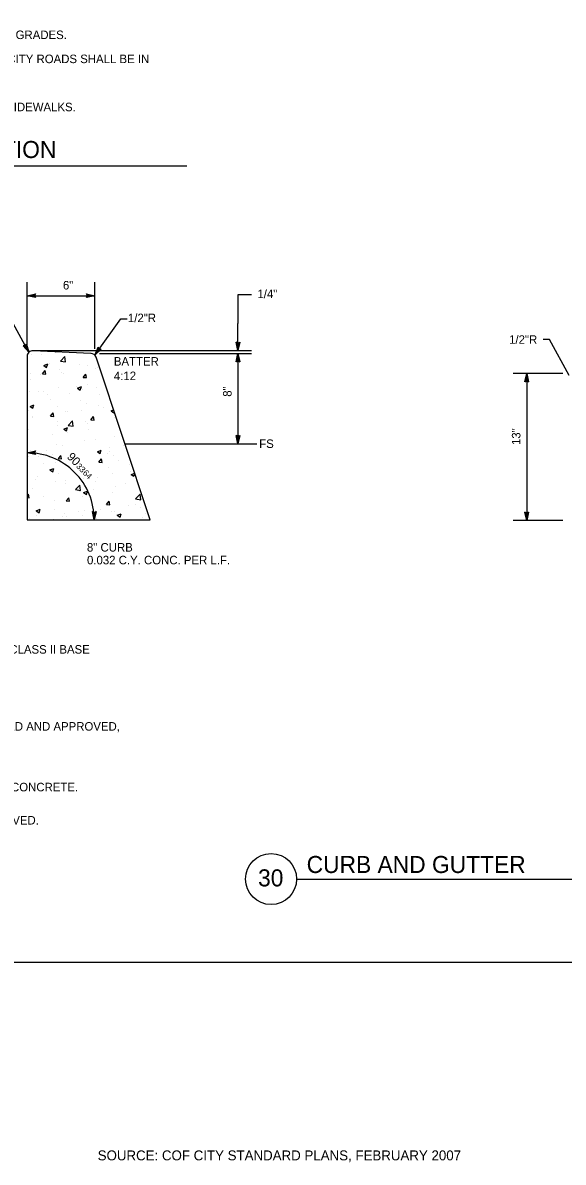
# Model space of a CAD drawing. Extents: x -119017 to -116080, y -104449 to -102845.
# Drawn here: x -118448 to -118067, y -104436 to -103633 of the extents above; entities that cross this region are included whole.
import ezdxf

# ---------------------------------------------------------------- set-up
doc = ezdxf.new("R2010")
doc.units = 0
for name, color, linetype in [('Default', 7, 'Continuous'), ('G-MARK', 7, 'Continuous'), ('G-TEXT', 7, 'Continuous'), ('Misc CnstDet(22)', 7, 'Continuous'), ('Nongeo Data(60)', 7, 'Continuous')]:
    doc.layers.add(name, color=color, linetype=linetype)

msp = doc.modelspace()

# ---------------------------------------------------------------- linework, layer by layer
at = {"layer": 'Default'}
msp.add_lwpolyline([(-119016.83, -102845.16), (-117223.08, -102845.16), (-117223.08, -104295.16), (-119016.83, -104295.16)], close=True, dxfattribs=at)
at = {"layer": 'G-MARK'}
for p, q in [((-118444.83, -103860.58), (-118444.83, -103815.86)), ((-118397.18, -103862.74), (-118397.18, -103815.86)), ((-118444.83, -103825.37), (-118397.18, -103825.37)), ((-118286.88, -103824.65), (-118296.42, -103824.65)), ((-118296.42, -103824.65), (-118296.42, -103844.85)), ((-118296.42, -103863.93), (-118296.42, -103844.85)), ((-118441.49, -103863.93), (-118286.88, -103863.93)), ((-118393.83, -103866.09), (-118286.88, -103866.09)), ((-118296.42, -103866.09), (-118296.42, -103885.16)), ((-118296.42, -103875.62), (-118296.42, -103929.63)), ((-118067.57, -103880.19), (-118102.56, -103880.19)), ((-118093.02, -103880.19), (-118093.02, -103983.63)), ((-118067.57, -103983.63), (-118102.56, -103983.63))]:
    msp.add_line(p, q, dxfattribs=at)
for points in [[(-118443.61, -103865.21), (-118457.25, -103840.22), (-118461.72, -103840.22)], [(-118397.27, -103867.12), (-118378.82, -103841.69), (-118374.35, -103841.69)], [(-118063.03, -103881.5), (-118077.01, -103856.14), (-118081.48, -103856.14)]]:
    msp.add_lwpolyline(points, dxfattribs=at)
msp.add_arc((-118444.83, -103983.25), 47.27, 359.98371, 90.00008, dxfattribs=at)
at = {"layer": 'G-TEXT'}
for points in [[(-118438.93, -103826.69), (-118444.83, -103825.37), (-118438.93, -103824.06), (-118439.14, -103824.41), (-118443.46, -103825.37), (-118439.14, -103826.34), (-118439.34, -103825.99), (-118442.11, -103825.37), (-118439.35, -103824.76), (-118439.56, -103825.11), (-118440.75, -103825.37), (-118439.55, -103825.64), (-118439.71, -103825.37), (-118438.93, -103824.06), (-118439.71, -103825.37)], [(-118403.08, -103824.05), (-118397.18, -103825.37), (-118403.08, -103826.68), (-118402.87, -103826.33), (-118398.55, -103825.37), (-118402.87, -103824.4), (-118402.66, -103824.75), (-118399.9, -103825.37), (-118402.66, -103825.98), (-118402.45, -103825.63), (-118401.25, -103825.37), (-118402.46, -103825.1), (-118402.29, -103825.37), (-118403.08, -103826.68), (-118402.29, -103825.37)], [(-118445.3, -103859.4), (-118443.61, -103865.21), (-118447.61, -103860.67), (-118447.2, -103860.68), (-118444.28, -103864.01), (-118445.51, -103859.75), (-118445.71, -103860.1), (-118444.92, -103862.83), (-118446.79, -103860.7), (-118446.39, -103860.71), (-118445.58, -103861.63), (-118445.92, -103860.45), (-118446.08, -103860.73), (-118447.61, -103860.67), (-118446.08, -103860.73)], [(-118392.75, -103863.09), (-118397.27, -103867.12), (-118394.89, -103861.56), (-118394.73, -103861.93), (-118396.47, -103866), (-118393.16, -103863.06), (-118393.56, -103863.02), (-118395.68, -103864.91), (-118394.57, -103862.31), (-118394.4, -103862.68), (-118394.89, -103863.81), (-118393.97, -103862.99), (-118394.28, -103862.96), (-118394.89, -103861.56), (-118394.28, -103862.96)], [(-118295.1, -103858.02), (-118296.42, -103863.93), (-118297.73, -103858.02), (-118297.38, -103858.23), (-118296.42, -103862.56), (-118295.45, -103858.23), (-118295.8, -103858.44), (-118296.42, -103861.21), (-118297.03, -103858.44), (-118296.68, -103858.65), (-118296.42, -103859.85), (-118296.15, -103858.65), (-118296.42, -103858.81), (-118297.73, -103858.02), (-118296.42, -103858.81)], [(-118297.74, -103871.99), (-118296.42, -103866.09), (-118295.11, -103871.99), (-118295.46, -103871.78), (-118296.42, -103867.46), (-118297.39, -103871.78), (-118297.04, -103871.57), (-118296.42, -103868.81), (-118295.81, -103871.57), (-118296.16, -103871.36), (-118296.42, -103870.17), (-118296.69, -103871.37), (-118296.42, -103871.2), (-118295.11, -103871.99), (-118296.42, -103871.2)], [(-118094.34, -103886.09), (-118093.02, -103880.19), (-118091.71, -103886.1), (-118092.06, -103885.89), (-118093.02, -103881.56), (-118093.99, -103885.89), (-118093.64, -103885.68), (-118093.02, -103882.91), (-118092.41, -103885.68), (-118092.76, -103885.46), (-118093.03, -103884.27), (-118093.29, -103885.47), (-118093.02, -103885.31), (-118091.71, -103886.1), (-118093.02, -103885.31)], [(-118295.1, -103923.72), (-118296.42, -103929.63), (-118297.73, -103923.72), (-118297.38, -103923.93), (-118296.42, -103928.26), (-118295.45, -103923.93), (-118295.8, -103924.14), (-118296.42, -103926.91), (-118297.03, -103924.14), (-118296.68, -103924.35), (-118296.42, -103925.55), (-118296.15, -103924.35), (-118296.42, -103924.51), (-118297.73, -103923.72), (-118296.42, -103924.51)], [(-118438.93, -103937.3), (-118444.83, -103935.98), (-118438.93, -103934.67), (-118439.14, -103935.02), (-118443.46, -103935.97), (-118439.14, -103936.95), (-118439.34, -103936.6), (-118442.11, -103935.98), (-118439.35, -103935.37), (-118439.56, -103935.71), (-118440.75, -103935.98), (-118439.55, -103936.25), (-118439.71, -103935.98), (-118438.93, -103934.67), (-118439.71, -103935.98)], [(-118396.26, -103977.35), (-118397.58, -103983.26), (-118398.89, -103977.35), (-118398.54, -103977.56), (-118397.59, -103981.89), (-118396.61, -103977.56), (-118396.96, -103977.77), (-118397.58, -103980.54), (-118398.19, -103977.77), (-118397.84, -103977.98), (-118397.58, -103979.18), (-118397.31, -103977.98), (-118397.58, -103978.14), (-118398.89, -103977.35), (-118397.58, -103978.14)], [(-118091.7, -103977.73), (-118093.02, -103983.63), (-118094.33, -103977.73), (-118093.98, -103977.94), (-118093.03, -103982.27), (-118092.05, -103977.94), (-118092.4, -103978.15), (-118093.02, -103980.92), (-118093.63, -103978.15), (-118093.29, -103978.36), (-118093.02, -103979.56), (-118092.75, -103978.35), (-118093.02, -103978.52), (-118094.33, -103977.73), (-118093.02, -103978.52)]]:
    msp.add_lwpolyline(points, close=True, dxfattribs=at)
at = {"layer": 'Misc CnstDet(22)'}
for p, q in [((-118397.18, -103825.37), (-118397.18, -103825.37)), ((-118444.83, -103863.93), (-118444.83, -103863.93)), ((-118444.83, -103863.93), (-118444.83, -103863.93)), ((-118444.83, -103863.93), (-118444.83, -103863.93)), ((-118399.87, -103865.96), (-118440.67, -103864.12)), ((-118444.83, -103868.09), (-118444.83, -103983.26)), ((-118442.11, -103866.62), (-118442.11, -103866.62)), ((-118434.92, -103866.81), (-118434.92, -103866.81)), ((-118424.98, -103865.49), (-118424.98, -103865.49)), ((-118421.32, -103871.43), (-118418.22, -103868.21)), ((-118421.32, -103871.43), (-118417.78, -103871.97)), ((-118417.78, -103871.97), (-118418.22, -103868.21)), ((-118397.18, -103866.09), (-118397.18, -103866.09)), ((-118397.18, -103866.09), (-118397.18, -103866.09)), ((-118397.18, -103866.09), (-118397.18, -103866.09)), ((-118358.09, -103983.26), (-118396.3, -103868.62)), ((-118296.42, -103866.09), (-118296.42, -103866.09)), ((-118442.61, -103879.85), (-118442.61, -103879.85)), ((-118433.95, -103880.38), (-118432.04, -103878.09)), ((-118433.95, -103880.38), (-118431.57, -103880.56)), ((-118433.14, -103874.5), (-118430.35, -103873.43)), ((-118433.14, -103874.5), (-118431.17, -103875.81)), ((-118431.57, -103880.56), (-118432.04, -103878.09)), ((-118431.17, -103875.81), (-118430.35, -103873.43)), ((-118428.82, -103872.78), (-118428.82, -103872.78)), ((-118422.22, -103877.06), (-118422.22, -103877.06)), ((-118420.38, -103879.19), (-118420.38, -103879.19)), ((-118419.5, -103880.41), (-118419.5, -103880.41)), ((-118407.62, -103873.65), (-118407.62, -103873.65)), ((-118402.15, -103874.5), (-118402.15, -103874.5)), ((-118396.36, -103876.44), (-118396.36, -103876.44)), ((-118395.3, -103875.87), (-118395.3, -103875.87)), ((-118442.68, -103884.38), (-118442.68, -103884.38)), ((-118435.42, -103881.16), (-118435.42, -103881.16)), ((-118405.46, -103882.85), (-118403.56, -103880.56)), ((-118405.46, -103882.85), (-118403.09, -103883.07)), ((-118403.09, -103883.07), (-118403.56, -103880.56)), ((-118402.65, -103887.73), (-118402.65, -103887.73)), ((-118443.08, -103893.07), (-118443.08, -103893.07)), ((-118436.55, -103893.07), (-118436.55, -103893.07)), ((-118433.17, -103893.1), (-118433.17, -103893.1)), ((-118430.82, -103894.86), (-118430.82, -103894.86)), ((-118422.69, -103890.26), (-118422.69, -103890.26)), ((-118415.34, -103893.95), (-118415.34, -103893.95)), ((-118410, -103889.13), (-118410, -103889.13)), ((-118409.43, -103890.48), (-118406.65, -103889.41)), ((-118409.43, -103890.48), (-118407.46, -103891.82)), ((-118407.46, -103891.82), (-118406.65, -103889.41)), ((-118405.74, -103891.54), (-118405.74, -103891.54)), ((-118395.8, -103890.23), (-118395.8, -103890.23)), ((-118394.14, -103894.86), (-118394.14, -103894.86)), ((-118442.8, -103903.3), (-118440.02, -103902.24)), ((-118442.8, -103903.3), (-118440.83, -103904.61)), ((-118440.83, -103904.61), (-118440.02, -103902.24)), ((-118428.17, -103898.39), (-118428.17, -103898.39)), ((-118423.19, -103903.49), (-118423.19, -103903.49)), ((-118406.96, -103899.3), (-118406.96, -103899.3)), ((-118403.12, -103900.95), (-118403.12, -103900.95)), ((-118394.83, -103903.02), (-118394.83, -103903.02)), ((-118391.2, -103903.92), (-118391.2, -103903.92)), ((-118385.76, -103900.2), (-118385.76, -103900.2)), ((-118443.58, -103906.3), (-118443.58, -103906.3)), ((-118441.27, -103910.52), (-118441.27, -103910.52)), ((-118441.14, -103910.96), (-118441.14, -103910.96)), ((-118428.45, -103910.24), (-118426.51, -103907.96)), ((-118428.45, -103910.24), (-118426.07, -103910.46)), ((-118426.07, -103910.46), (-118426.51, -103907.96)), ((-118418, -103906.99), (-118418, -103906.99)), ((-118416.19, -103907.21), (-118416.19, -103907.21)), ((-118406.24, -103905.89), (-118406.24, -103905.89)), ((-118399.96, -103912.74), (-118398.02, -103910.46)), ((-118397.58, -103912.93), (-118398.02, -103910.46)), ((-118385.73, -103906.49), (-118383.92, -103905.77)), ((-118385.73, -103906.49), (-118383.76, -103907.8)), ((-118383.76, -103907.8), (-118383.48, -103907.02)), ((-118382.98, -103911.18), (-118382.98, -103911.18)), ((-118444.46, -103913.24), (-118444.46, -103913.24)), ((-118444.05, -103919.5), (-118444.05, -103919.5)), ((-118423.66, -103916.71), (-118423.66, -103916.71)), ((-118423.26, -103914.15), (-118423.26, -103914.15)), ((-118419.1, -103919.28), (-118416.31, -103918.22)), ((-118419.1, -103919.28), (-118417.13, -103920.62)), ((-118417.13, -103920.62), (-118416.31, -103918.22)), ((-118416.06, -103916.68), (-118412.97, -103913.46)), ((-118416.06, -103916.68), (-118412.53, -103917.25)), ((-118412.53, -103917.25), (-118412.97, -103913.46)), ((-118403.62, -103914.18), (-118403.62, -103914.18)), ((-118402.05, -103915.06), (-118402.05, -103915.06)), ((-118401.68, -103919.59), (-118401.68, -103919.59)), ((-118399.96, -103912.74), (-118397.58, -103912.93)), ((-118380.85, -103915.93), (-118380.85, -103915.93)), ((-118426.66, -103922.87), (-118426.66, -103922.87)), ((-118416.72, -103921.56), (-118416.72, -103921.56)), ((-118404.09, -103927.38), (-118404.09, -103927.38)), ((-118396.49, -103926.72), (-118396.49, -103926.72)), ((-118383.45, -103924.41), (-118383.45, -103924.41)), ((-118444.55, -103932.72), (-118444.55, -103932.72)), ((-118442.8, -103934.66), (-118442.8, -103934.66)), ((-118430.98, -103934.44), (-118430.98, -103934.44)), ((-118424.13, -103929.94), (-118424.13, -103929.94)), ((-118419.63, -103930.69), (-118419.63, -103930.69)), ((-118395.39, -103935.26), (-118392.61, -103934.19)), ((-118395.39, -103935.26), (-118393.42, -103936.6)), ((-118393.42, -103936.6), (-118392.61, -103934.19)), ((-118388.58, -103936.23), (-118388.58, -103936.23)), ((-118387.04, -103931.94), (-118387.04, -103931.94)), ((-118386.95, -103935.45), (-118386.95, -103935.45)), ((-118377.1, -103930.63), (-118377.1, -103930.63)), ((-118375.94, -103929.63), (-118283, -103929.63)), ((-118297.89, -103929.63), (-118297.89, -103929.63)), ((-118296.42, -103929.63), (-118296.42, -103929.63)), ((-118443.8, -103938.89), (-118443.8, -103938.89)), ((-118437.11, -103938.54), (-118437.11, -103938.54)), ((-118433.29, -103943.39), (-118433.29, -103943.39)), ((-118427.16, -103937.23), (-118427.16, -103937.23)), ((-118424.63, -103943.14), (-118424.63, -103943.14)), ((-118422.91, -103940.1), (-118421, -103937.82)), ((-118422.91, -103940.1), (-118420.54, -103940.32)), ((-118422.6, -103939.79), (-118422.6, -103939.79)), ((-118420.54, -103940.32), (-118421, -103937.82)), ((-118394.42, -103942.61), (-118392.52, -103940.32)), ((-118394.42, -103942.61), (-118392.08, -103942.83)), ((-118392.05, -103942.83), (-118392.52, -103940.32)), ((-118383.95, -103937.63), (-118383.95, -103937.63)), ((-118380.2, -103941.57), (-118380.2, -103941.57)), ((-118372.5, -103944.33), (-118372.5, -103944.33)), ((-118428.76, -103948.08), (-118425.98, -103947.02)), ((-118428.76, -103948.08), (-118426.79, -103949.42)), ((-118426.79, -103949.42), (-118425.98, -103947.02)), ((-118422.57, -103950.92), (-118422.57, -103950.92)), ((-118387.54, -103946.3), (-118387.54, -103946.3)), ((-118384.42, -103950.86), (-118384.42, -103950.86)), ((-118371.78, -103949.33), (-118371.78, -103949.33)), ((-118371.69, -103951.27), (-118369.09, -103950.27)), ((-118371.69, -103951.27), (-118369.72, -103952.58)), ((-118369.72, -103952.58), (-118369, -103950.49)), ((-118444.83, -103958.43), (-118444.83, -103958.43)), ((-118438.89, -103954.65), (-118438.89, -103954.65)), ((-118437.61, -103952.89), (-118437.61, -103952.89)), ((-118425.1, -103956.37), (-118425.1, -103956.37)), ((-118418.1, -103957.3), (-118418.1, -103957.3)), ((-118417.69, -103955.52), (-118417.69, -103955.52)), ((-118410.81, -103961.93), (-118407.71, -103958.71)), ((-118407.28, -103962.5), (-118407.71, -103958.71)), ((-118405.06, -103953.83), (-118405.06, -103953.83)), ((-118403.9, -103959.62), (-118403.9, -103959.62)), ((-118396.49, -103956.43), (-118396.49, -103956.43)), ((-118394.96, -103953.3), (-118394.96, -103953.3)), ((-118382.95, -103959.99), (-118382.95, -103959.99)), ((-118375.29, -103957.3), (-118375.29, -103957.3)), ((-118444.83, -103966.22), (-118443.99, -103965.22)), ((-118444.83, -103967.59), (-118443.52, -103967.69)), ((-118443.52, -103967.69), (-118443.99, -103965.22)), ((-118441.27, -103961.28), (-118441.27, -103961.28)), ((-118433.01, -103966.59), (-118433.01, -103966.59)), ((-118417.41, -103969.97), (-118415.5, -103967.69)), ((-118415.03, -103970.19), (-118415.5, -103967.69)), ((-118410.81, -103961.93), (-118407.28, -103962.5)), ((-118407.93, -103963.28), (-118407.93, -103963.28)), ((-118405.53, -103967.06), (-118405.53, -103967.06)), ((-118405.06, -103964.06), (-118402.27, -103963)), ((-118405.06, -103964.06), (-118403.09, -103965.4)), ((-118403.09, -103965.4), (-118402.27, -103963)), ((-118397.99, -103961.96), (-118397.99, -103961.96)), ((-118384.92, -103964.09), (-118384.92, -103964.09)), ((-118368.41, -103968.53), (-118365.31, -103965.28)), ((-118368.41, -103968.53), (-118364.87, -103969.06)), ((-118364.87, -103969.06), (-118365.31, -103965.28)), ((-118438.42, -103976.88), (-118435.64, -103975.82)), ((-118436.45, -103978.22), (-118435.64, -103975.82)), ((-118425.6, -103969.59), (-118425.6, -103969.59)), ((-118425.41, -103975.82), (-118425.41, -103975.82)), ((-118417.41, -103969.97), (-118415.03, -103970.19)), ((-118404.21, -103976.72), (-118404.21, -103976.72)), ((-118393.39, -103975.66), (-118393.39, -103975.66)), ((-118388.92, -103972.47), (-118387.01, -103970.19)), ((-118388.92, -103972.47), (-118386.54, -103972.69)), ((-118386.54, -103972.69), (-118387.01, -103970.19)), ((-118373.44, -103973.03), (-118373.44, -103973.03)), ((-118368.31, -103972.35), (-118368.31, -103972.35)), ((-118365, -103974.5), (-118365, -103974.5)), ((-118444.83, -103983.26), (-118358.09, -103983.26)), ((-118444.83, -103983.26), (-118444.83, -103983.26)), ((-118444.83, -103983.26), (-118444.83, -103983.26)), ((-118444.83, -103983.26), (-118444.83, -103983.26)), ((-118443.46, -103982.23), (-118443.46, -103982.23)), ((-118438.42, -103976.88), (-118436.45, -103978.22)), ((-118438.23, -103980.26), (-118438.23, -103980.26)), ((-118432.42, -103983.26), (-118432.42, -103983.26)), ((-118426.07, -103982.82), (-118426.07, -103982.82)), ((-118419.75, -103980.98), (-118419.75, -103980.98)), ((-118418.38, -103978.94), (-118418.38, -103978.94)), ((-118417.03, -103981.16), (-118417.03, -103981.16)), ((-118408.43, -103977.63), (-118408.43, -103977.63)), ((-118406.03, -103980.29), (-118406.03, -103980.29)), ((-118396.58, -103977), (-118396.58, -103977)), ((-118395.83, -103982.04), (-118395.83, -103982.04)), ((-118385.39, -103977.29), (-118385.39, -103977.29)), ((-118383.01, -103977.6), (-118383.01, -103977.6)), ((-118381.35, -103980.07), (-118378.57, -103979.01)), ((-118381.35, -103980.07), (-118379.38, -103981.38)), ((-118379.38, -103981.38), (-118378.57, -103979.01)), ((-118374.63, -103982.95), (-118374.63, -103982.95)), ((-118363.9, -103981.76), (-118363.9, -103981.76)), ((-118361.81, -103978.51), (-118361.81, -103978.51)), ((-118093.02, -103983.63), (-118093.02, -103983.63))]:
    msp.add_line(p, q, dxfattribs=at)
for centre, start, end in [((-118440.86, -103868.08), 87.39744, 180), ((-118400.04, -103869.93), 19.1899, 87.39744)]:
    msp.add_arc(centre, 3.97, start, end, dxfattribs=at)
at = {"layer": 'Nongeo Data(60)'}
for p, q in [((-118708.74, -103733.93), (-118332.37, -103733.93)), ((-118255.04, -104236.34), (-118040.28, -104236.34))]:
    msp.add_line(p, q, dxfattribs=at)
msp.add_circle((-118273.04, -104236.34), 18, dxfattribs=at)

# ---------------------------------------------------------------- texts
at = {"layer": 'Misc CnstDet(22)'}
for s, height, p in [('SURFACE OF VAULTS OR MANHOLES MUST MATCH PAVEMENT AND PARKWAY GRADES.', 6, (-118765.45, -103644.5)), ('REPAIR OF TRENCHES AND REPLACEMENT OF PAVED SURFACE IN EXISTING CITY ROADS SHALL BE IN', 6, (-118765.45, -103661.45)), ('WHENEVER POSSIBLE, MANHOLE COVERS SHALL NOT BE PLACED WITH THE SIDEWALKS.', 6, (-118765.45, -103695.35)), ('UNDERGROUND UTILITY LOCATION', 12, (-118703.31, -103728.3)), ('6"', 6, (-118419.64, -103820.94)), ('1/2"R', 6, (-118373.85, -103843.97)), ('1/2"R', 6, (-118105.41, -103859.22)), ('BATTER', 6, (-118383.76, -103874.59)), ('4:12', 6, (-118383.76, -103884.79)), ('FS', 6, (-118281.39, -103932.6)), ('8" CURB', 6, (-118402.72, -104005.62)), ('0.032 C.Y. CONC. PER L.F.', 6, (-118402.68, -104014.61)), ('RELATIVE COMPACTION REQUIREMENT FOR TOP 12" OF SUBGRADE IS 95% WHEN CLASS II BASE', 6, (-118783.87, -104077.52)), ('NO FORMS SHALL BE PLACED UNTIL THE RELATIVE COMPACTION HAS BEEN TESTED AND APPROVED,', 6, (-118783.87, -104131.78)), ('ALL FORMWORK SHALL BE INSPECTED AND APPROVED PRIOR TO PLACEMENT OF CONCRETE.', 6, (-118783.87, -104174.56)), ('THE CONTRACTOR SHALL USE 520-C-2500 CONCRETE UNLESS OTHERWISE APPROVED.', 6, (-118783.87, -104197.92)), ('CURB AND GUTTER', 12, (-118248, -104232.09)), ('30', 12, (-118282.21, -104241.53)), ('SOURCE: COF CITY STANDARD PLANS, FEBRUARY 2007', 7, (-118395.16, -104434.57))]:
    msp.add_text(s, height=height, dxfattribs=at).set_placement(p)
for s, height, rotation, p in [('1/4"', 6, 0.001, (-118282.65, -103827.06)), ('8"', 6, 90, (-118300.85, -103896.51)), ('13"', 6, 90, (-118097.45, -103930.54)), ('90', 6, 315, (-118417.24, -103939.35)), ('33', 4.2, 315, (-118410.65, -103945.94)), ('64', 4.2, 315, (-118406.03, -103950.55))]:
    msp.add_text(s, height=height, rotation=rotation, dxfattribs=at).set_placement(p)

doc.saveas('drawing.dxf')
